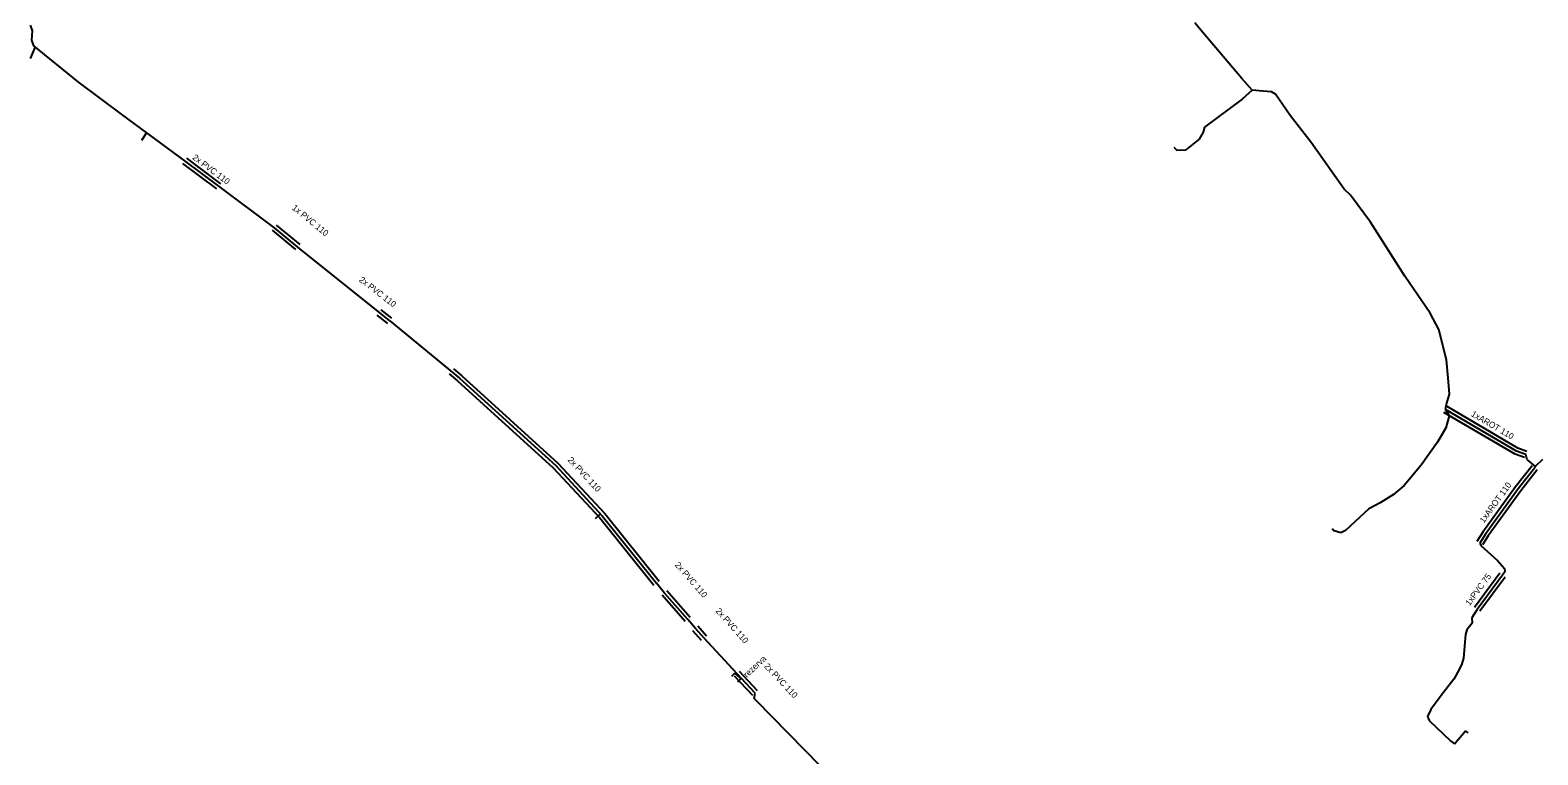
# Model space of a CAD drawing. Extents: x -651943 to -618711, y -1138561 to -1100552.
# Drawn here: x -648984.6 to -648800.9, y -1112034.7 to -1111946.3 of the extents above; entities that cross this region are included whole.
import ezdxf

# ---------------------------------------------------------------- set-up
doc = ezdxf.new("R2010")
doc.units = 0
doc.layers.add('KT trasa', color=7, linetype='Continuous')
doc.layers.add('KT zařízení', color=7, linetype='Continuous')

# ---------------------------------------------------------------- blocks, each defined once
blk = doc.blocks.new('TVREZ')
at = {"layer": 'KT zařízení'}
for p, q in [((-0.05, 0.05), (0, 0.05)), ((0, -0.05), (0, 0.05)), ((-0.05, -0.05), (0, -0.05))]:
    blk.add_line(p, q, dxfattribs=at)

msp = doc.modelspace()

# ---------------------------------------------------------------- linework, layer by layer
at = {"layer": 'KT trasa'}
for p, q in [((-648984.34, -1111946.42), (-648984.61, -1111945.75)), ((-648984.45, -1111947.55), (-648984.34, -1111946.42)), ((-648841.95, -1111946.34), (-648842.68, -1111945.43)), ((-648836.96, -1111952.24), (-648841.95, -1111946.34)), ((-648984.05, -1111948.36), (-648984.65, -1111949.79)), ((-648984.21, -1111948.23), (-648984.45, -1111947.55)), ((-648978.8, -1111952.65), (-648984.21, -1111948.23)), ((-648973.34, -1111956.71), (-648978.8, -1111952.65)), ((-648835.69, -1111953.64), (-648836.96, -1111952.24)), ((-648835.69, -1111953.64), (-648836.91, -1111954.76)), ((-648834.4, -1111953.76), (-648835.69, -1111953.64)), ((-648833.36, -1111953.84), (-648834.4, -1111953.76)), ((-648832.86, -1111954.12), (-648833.36, -1111953.84)), ((-648836.91, -1111954.76), (-648841.51, -1111958.16)), ((-648831.07, -1111956.74), (-648832.86, -1111954.12)), ((-648965.8, -1111962.26), (-648973.34, -1111956.71)), ((-648828.5, -1111960.03), (-648831.07, -1111956.74)), ((-648970.45, -1111958.84), (-648971.07, -1111959.8)), ((-648841.67, -1111958.79), (-648842.18, -1111959.61)), ((-648841.51, -1111958.16), (-648841.67, -1111958.79)), ((-648845.25, -1111960.58), (-648844.89, -1111960.97)), ((-648844.89, -1111960.97), (-648843.79, -1111960.93)), ((-648842.18, -1111959.61), (-648843.79, -1111960.93)), ((-648824.5, -1111965.7), (-648828.5, -1111960.03)), ((-648961.66, -1111965.37), (-648965.8, -1111962.26)), ((-648954.87, -1111970.41), (-648961.66, -1111965.37)), ((-648823.71, -1111966.43), (-648824.5, -1111965.7)), ((-648821.26, -1111969.75), (-648823.71, -1111966.43)), ((-648952, -1111972.77), (-648954.87, -1111970.41)), ((-648817.09, -1111976.31), (-648821.26, -1111969.75)), ((-648940.81, -1111981.75), (-648952, -1111972.77)), ((-648813.99, -1111980.84), (-648817.09, -1111976.31)), ((-648812.96, -1111982.82), (-648813.99, -1111980.84)), ((-648940.81, -1111981.75), (-648932.3, -1111988.76)), ((-648812.02, -1111986.53), (-648812.96, -1111982.82)), ((-648811.78, -1111989.2), (-648812.02, -1111986.53)), ((-648932.3, -1111988.76), (-648920.59, -1111999.38)), ((-648812.03, -1111991.91), (-648811.66, -1111990.7)), ((-648811.66, -1111990.7), (-648811.78, -1111989.2)), ((-648812.15, -1111992.57), (-648812.03, -1111991.91)), ((-648812.15, -1111992.57), (-648811.68, -1111993.34)), ((-648803.48, -1111997.64), (-648812.15, -1111992.57)), ((-648811.68, -1111993.34), (-648812.11, -1111994.8)), ((-648812.11, -1111994.8), (-648813.1, -1111996.55)), ((-648813.1, -1111996.55), (-648815.12, -1111999.37)), ((-648802.35, -1111998.06), (-648803.48, -1111997.64)), ((-648802.18, -1111998.69), (-648802.35, -1111998.06)), ((-648920.59, -1111999.38), (-648914.91, -1112005.51)), ((-648815.12, -1111999.37), (-648817.18, -1112001.82)), ((-648801.26, -1111999.68), (-648803.28, -1112002.23)), ((-648802.18, -1111998.69), (-648801.22, -1111999.52)), ((-648801.22, -1111999.52), (-648801.26, -1111999.68)), ((-648801.22, -1111999.52), (-648800.26, -1111998.61)), ((-648818.46, -1112002.94), (-648820.09, -1112003.95)), ((-648817.18, -1112001.82), (-648818.46, -1112002.94)), ((-648803.28, -1112002.23), (-648807.26, -1112007.74)), ((-648915.75, -1112005.87), (-648915.12, -1112005.29)), ((-648821.5, -1112004.69), (-648824.34, -1112007.3)), ((-648820.09, -1112003.95), (-648821.5, -1112004.69)), ((-648914.91, -1112005.51), (-648908.3, -1112013.74)), ((-648825.96, -1112007.06), (-648825.69, -1112007.36)), ((-648824.34, -1112007.3), (-648824.9, -1112007.61)), ((-648824.9, -1112007.61), (-648825.69, -1112007.36)), ((-648807.26, -1112007.74), (-648807.97, -1112008.86)), ((-648807.97, -1112008.86), (-648807.84, -1112009.15)), ((-648807.84, -1112009.15), (-648805.78, -1112010.95)), ((-648805.78, -1112010.95), (-648804.94, -1112011.95)), ((-648805.19, -1112012.74), (-648808.29, -1112016.92)), ((-648804.92, -1112012.36), (-648805.19, -1112012.74)), ((-648804.94, -1112011.95), (-648804.92, -1112012.36)), ((-648907.33, -1112014.93), (-648908.3, -1112013.74)), ((-648904.5, -1112018.16), (-648907.33, -1112014.93)), ((-648903.57, -1112019.26), (-648904.5, -1112018.16)), ((-648808.29, -1112016.92), (-648808.93, -1112017.97)), ((-648808.93, -1112017.97), (-648808.9, -1112018.61)), ((-648902.51, -1112020.44), (-648903.57, -1112019.26)), ((-648809.71, -1112019.97), (-648809.96, -1112022.85)), ((-648809.52, -1112019.43), (-648809.71, -1112019.97)), ((-648808.9, -1112018.61), (-648809.52, -1112019.43)), ((-648898.49, -1112024.78), (-648902.51, -1112020.44)), ((-648810.13, -1112023.56), (-648810.48, -1112024.27)), ((-648809.96, -1112022.85), (-648810.13, -1112023.56)), ((-648896.28, -1112027.14), (-648898.49, -1112024.78)), ((-648811.14, -1112025.43), (-648812.67, -1112027.4)), ((-648810.48, -1112024.27), (-648811.14, -1112025.43)), ((-648896.4, -1112027.77), (-648896.28, -1112027.14)), ((-648812.67, -1112027.4), (-648813.91, -1112029.14)), ((-648896.4, -1112027.77), (-648896.19, -1112027.99)), ((-648896.19, -1112027.99), (-648888.36, -1112035.98)), ((-648813.91, -1112029.14), (-648814.33, -1112029.96)), ((-648814.33, -1112029.96), (-648814.13, -1112030.46)), ((-648814.13, -1112030.46), (-648811.53, -1112032.94)), ((-648811.53, -1112032.94), (-648811.05, -1112033.32)), ((-648811.05, -1112033.32), (-648809.7, -1112031.72)), ((-648809.38, -1112031.97), (-648809.7, -1112031.72))]:
    msp.add_line(p, q, dxfattribs=at)
at = {"layer": 'KT zařízení'}
for p, q in [((-648961.9, -1111965.69), (-648966.04, -1111962.58)), ((-648961.42, -1111965.05), (-648965.56, -1111961.94)), ((-648951.74, -1111972.46), (-648954.61, -1111970.1)), ((-648952.25, -1111973.08), (-648955.12, -1111970.72)), ((-648941.05, -1111982.07), (-648942.36, -1111981.06)), ((-648940.57, -1111981.43), (-648941.88, -1111980.42)), ((-648933.56, -1111988.24), (-648932.56, -1111989.06)), ((-648933.05, -1111987.62), (-648932.03, -1111988.46)), ((-648932.03, -1111988.46), (-648920.31, -1111999.1)), ((-648932.56, -1111989.06), (-648920.88, -1111999.66)), ((-648803.31, -1111997.28), (-648811.95, -1111992.22)), ((-648803.65, -1111998), (-648812.35, -1111992.92)), ((-648802.49, -1111998.43), (-648803.65, -1111998)), ((-648802.21, -1111997.69), (-648803.31, -1111997.28)), ((-648920.88, -1111999.66), (-648915.21, -1112005.78)), ((-648920.31, -1111999.1), (-648914.61, -1112005.24)), ((-648801.57, -1111999.43), (-648803.6, -1112001.99)), ((-648800.95, -1111999.93), (-648802.96, -1112002.47)), ((-648803.6, -1112001.99), (-648807.59, -1112007.51)), ((-648802.96, -1112002.47), (-648806.93, -1112007.97)), ((-648914.61, -1112005.24), (-648907.99, -1112013.49)), ((-648915.21, -1112005.78), (-648908.61, -1112013.99)), ((-648807.59, -1112007.51), (-648808.31, -1112008.65)), ((-648806.93, -1112007.97), (-648807.63, -1112009.07)), ((-648805.51, -1112012.5), (-648808.61, -1112016.68)), ((-648804.87, -1112012.98), (-648807.97, -1112017.16)), ((-648904.8, -1112018.42), (-648907.63, -1112015.19)), ((-648904.2, -1112017.9), (-648907.03, -1112014.67)), ((-648902.81, -1112020.71), (-648903.87, -1112019.53)), ((-648902.21, -1112020.17), (-648903.27, -1112018.99)), ((-648896.57, -1112027.41), (-648898.78, -1112025.05)), ((-648895.99, -1112026.87), (-648898.2, -1112024.51))]:
    msp.add_line(p, q, dxfattribs=at)

# ---------------------------------------------------------------- block references
at = {"layer": 'KT zařízení', "xscale": 9.999976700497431, "yscale": 9.999976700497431, "rotation": 45.6869270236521}
msp.add_blockref('TVREZ', (-648898.4, -1112025.04), dxfattribs=at)

# ---------------------------------------------------------------- texts
at = {"layer": 'KT zařízení'}
for s, rotation, p in [('2x PVC 110', 323.0858, (-648964.94, -1111961.99)), ('1x PVC 110', 320.5695, (-648952.8, -1111968.11)), ('2x PVC 110', 322.3681, (-648944.63, -1111976.89)), ('1xAROT 110', 329.6801, (-648809.09, -1111993.32)), ('2x PVC 110', 312.851, (-648919.19, -1111998.76)), ('1xAROT 110', 54.1559, (-648807.45, -1112006.47)), ('2x PVC 110', 311.2236, (-648906.12, -1112011.55)), ('1xPVC 75', 53.4384, (-648809.2, -1112016.54)), ('2x PVC 110', 311.9335, (-648901.16, -1112017.16)), ('rezerva', 42.8079, (-648897.29, -1112025.29)), ('2x PVC 110', 313.1201, (-648895.23, -1112023.91))]:
    msp.add_text(s, height=0.75, rotation=rotation, dxfattribs=at).set_placement(p)

doc.saveas('drawing.dxf')
